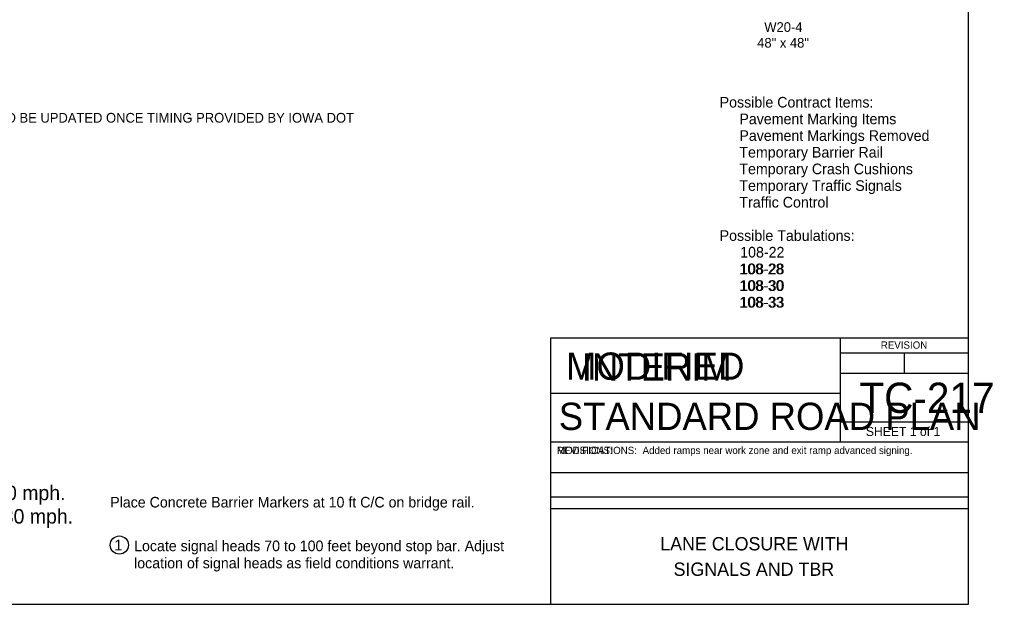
# Model space of a CAD drawing. Extents: x -2134934 to -2122394, y -2139046 to -2137036.
# Drawn here: x -2128661 to -2127057, y -2139046 to -2138081 of the extents above; entities that cross this region are included whole.
import ezdxf

# ---------------------------------------------------------------- set-up
doc = ezdxf.new("R2010")
doc.units = 0
for name, color, linetype in [('Barrier', 7, 'Continuous'), ('BridgeSuperStructureExisting', 7, 'Continuous'), ('Default', 7, 'Continuous'), ('Dimension', 7, 'Continuous'), ('dsnAlignmentCurveData', 7, 'Continuous'), ('dsnAlignmentTic', 7, 'Continuous'), ('dsnCellElements', 7, 'Continuous'), ('dsnStdLabel', 7, 'Continuous'), ('hwyPlanSheetShape', 7, 'Continuous')]:
    doc.layers.add(name, color=color, linetype=linetype)

msp = doc.modelspace()

# ---------------------------------------------------------------- linework, layer by layer
at = {"layer": 'BridgeSuperStructureExisting'}
msp.add_circle((-2128496.7, -2138947.8), 15, dxfattribs=at)
at = {"layer": 'Default'}
msp.add_lwpolyline([(-2130232, -2137035.9), (-2127097, -2137035.9), (-2127097, -2139045.9), (-2130232, -2139045.9)], close=True, dxfattribs=at)
at = {"layer": 'Dimension'}
for p, q in [((-2127307.9, -2138605.9), (-2127307.9, -2138697.3)), ((-2127307.9, -2138630.9), (-2127097, -2138630.9)), ((-2127202.4, -2138630.9), (-2127202.4, -2138664.1)), ((-2127307.9, -2138664.1), (-2127097, -2138664.1)), ((-2127785, -2138697.3), (-2127307.9, -2138697.3)), ((-2127307.9, -2138697.3), (-2127307.9, -2138777.3)), ((-2127097, -2138745.1), (-2127307.9, -2138745.1)), ((-2127785, -2138777.3), (-2127097, -2138777.3)), ((-2127785, -2138828.3), (-2127097, -2138828.3)), ((-2127785, -2138868.3), (-2127097, -2138868.3)), ((-2127785, -2138887.3), (-2127097, -2138887.3))]:
    msp.add_line(p, q, dxfattribs=at)
msp.add_lwpolyline([(-2127785, -2138605.9), (-2127097, -2138605.9), (-2127097, -2139045.9), (-2127785, -2139045.9)], close=True, dxfattribs=at)

# ---------------------------------------------------------------- texts
at = {"layer": 'Barrier'}
for s, p in [('W20-4', (-2127433, -2138101.1)), ('48" x 48"', (-2127444.7, -2138127.1))]:
    msp.add_text(s, height=16, dxfattribs=at).set_placement(p)
at = {"layer": 'BridgeSuperStructureExisting'}
for s, height, p in [('TO BE UPDATED ONCE TIMING PROVIDED BY IOWA DOT', 16, (-2128696.9, -2138250.8)), ('1', 17.5, (-2128504.8, -2138956.6)), ('Locate signal heads 70 to 100 feet beyond stop bar. Adjust ', 17.5, (-2128472.3, -2138957.9)), ('location of signal heads as field conditions warrant.', 17.5, (-2128472.3, -2138986.2))]:
    msp.add_text(s, height=height, dxfattribs=at).set_placement(p)
at = {"layer": 'Dimension'}
for s, height, p in [('REVISION', 12, (-2127240.9, -2138623.8)), ('TC-217', 50, (-2127276.2, -2138729.8)), ('STANDARD ROAD PLAN', 45.001, (-2127771.9, -2138757.9)), ('SHEET 1 of 1', 15, (-2127265.5, -2138767.9)), ('Added ramps near work zone and exit ramp advanced signing.', 12, (-2127633.7, -2138797.5)), ('LANE CLOSURE WITH', 22, (-2127604.6, -2138956.6)), ('SIGNALS AND TBR', 22, (-2127582.6, -2138998.6))]:
    msp.add_text(s, height=height, dxfattribs=at).set_placement(p)
at = {"layer": 'dsnAlignmentCurveData'}
msp.add_text('REVISIONS:', height=12, dxfattribs=at).set_placement((-2127775, -2138797.6))
at = {"layer": 'dsnAlignmentTic'}
for s, height, p in [('MODIFIED', 45, (-2127759.9, -2138675.1)), ('MODIFICATIONS:', 12, (-2127775, -2138797.6))]:
    msp.add_text(s, height=height, dxfattribs=at).set_placement(p)
at = {"layer": 'dsnCellElements'}
for s, p in [('Possible Contract Items:', (-2127506.6, -2138225.9)), ('     Pavement Marking Items', (-2127506.6, -2138253.4)), ('     Pavement Markings Removed', (-2127506.6, -2138280.9)), ('     Temporary Barrier Rail', (-2127506.6, -2138308.4)), ('     Temporary Crash Cushions', (-2127506.6, -2138335.9)), ('     Temporary Traffic Signals', (-2127506.6, -2138363.4)), ('     Traffic Control', (-2127506.6, -2138390.9)), ('Possible Tabulations:', (-2127506.6, -2138445.9)), ('108-22', (-2127472.7, -2138473.3)), ('108-22', (-2127472.7, -2138473.4)), ('     108-28', (-2127506.6, -2138500.9)), ('108-28', (-2127472.7, -2138500.9)), ('     108-30', (-2127506.6, -2138528.4)), ('108-30', (-2127472.7, -2138528.4)), ('     108-33', (-2127506.6, -2138555.9)), ('108-33', (-2127472.7, -2138555.9)), ('Place Concrete Barrier Markers at 10 ft C/C on bridge rail.', (-2128511.7, -2138885.8))]:
    msp.add_text(s, height=17.5, dxfattribs=at).set_placement(p)
at = {"layer": 'dsnStdLabel'}
for s, p in [('*All Red clearance value based on an operating speed of 20 mph.', (-2129520.3, -2138873.7)), ('**All Red clearance value based on an operating speed of 30 mph.', (-2129520.3, -2138912.4))]:
    msp.add_text(s, height=24, dxfattribs=at).set_placement(p)
at = {"layer": 'hwyPlanSheetShape'}
msp.add_text('INTERIM', height=45, dxfattribs=at).set_placement((-2127734, -2138676.3))

doc.saveas('drawing.dxf')
